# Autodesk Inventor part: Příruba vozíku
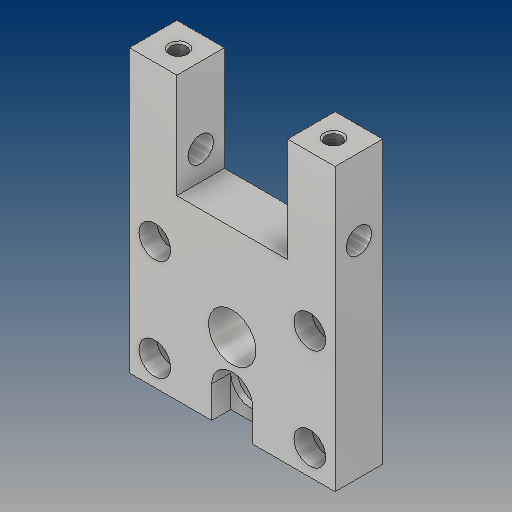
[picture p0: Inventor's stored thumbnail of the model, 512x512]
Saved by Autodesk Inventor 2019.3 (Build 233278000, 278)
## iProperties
Created: 2019-01
Part Number: Příruba vozíku
Material: Hliník 6061-AHC
Document SubType Name: Modeling
Designer: B-hon
Density: 2.7 g/cm^3
Appearance: Hliník – tmavý
Stock Number: 19-A4-P-21
Mass: 163.521 g
Surface Area: 177.073 cm^2
Volume: 60.5633 cm^3
Author: B-hon
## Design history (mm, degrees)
sketch "Náčrt1"
  geometry: L1 (-24.5, 16)-(24.5, 16); L2 (24.5, 16)-(24.5, -16); L3 (24.5, -16)-(-24.5, -16); L4 (-24.5, -16)-(-24.5, 16); L5 (-24.5, 16)-(24.5, -16); L6 (24.5, 16)-(-24.5, -16); L7 (32.5, -24)-(-32.5, -24); L8 (-32.5, -24)-(-32.5, 56); L9 (32.5, 56)-(32.5, -24); L10 (-32.5, 56)-(32.5, 56); 1 further point
  constraints: 20 end point, 3 horizontal, 3 parallel, 2 midpoint, 2 perpendicular
  dimensions: "d0" = 49 distance of L2.end L3.end; "d1" = 32 distance of L1.end L2.end; "d4" = 80 distance between parallel lines of L7 L10; "d21" = 8 distance between parallel lines of L9 L2; "d22" = 8 distance between parallel lines of L4 L8; "d23" = 8 distance between parallel lines of L7 L3
extrude "Vysunutí1" new body sketch "Náčrt1" distance "d5" = 12; taper "d6" = 0 deg
sketch "Náčrt2"
  geometry: L1 (0, 80)-(0, 0) reference; L2 (0, 0)-(-12, 0) reference; 2 further points
  dimensions: "d7" = 4.5 distance from line of L1 point (-4.5, 65); "d8" = 65 distance from line of L2 point (-4.5, 65)
hole "Díra1" sketch "Náčrt2" at (-4.5, 65) diameter "d9" = 8; stored, may be unused: countersink angle "d13" = 90 deg, drill point angle "d15" = 118 deg; dims "d10" = 6, "d11" = 4, "d12" = 2, "d14" = 8
sketch "Náčrt3"
  geometry: L1 (32.5, 56)-(-32.5, 56) reference; L2 (-17.5, 56)-(17.5, 56); L3 (17.5, 56)-(17.5, 32); L4 (17.5, 32)-(-17.5, 32); L5 (-17.5, 32)-(-17.5, 56); L6 (-32.5, -24)-(32.5, -24) reference; 1 further point
  constraints: 8 end point, 2 parallel, 1 horizontal, 1 perpendicular, 1 point on line
  dimensions: "d16" = 56 distance between parallel lines of L4 L6; "d17" = 35 distance of L3.end L4.end; "d18" = 15 distance from line of L1.end L5
extrude "Vysunutí2" cut sketch "Náčrt3" distance "d19" = 12; taper "d20" = 0 deg
sketch "Náčrt5"
  geometry: L1 (-24.5, 16)-(24.5, 16); L2 (24.5, 16)-(24.5, -16); L3 (24.5, -16)-(-24.5, -16); L4 (-24.5, -16)-(-24.5, 16); L5 (-24.5, 16)-(24.5, -16); L6 (24.5, 16)-(-24.5, -16); 5 further points
  constraints: 12 end point, 4 coincident, 2 midpoint, 2 parallel, 1 horizontal, 1 perpendicular
  dimensions: "d24" = 49 distance of L2.end L3.end; "d25" = 32 distance of L1.end L2.end
hole "Díra2" sketch "Náčrt5" at (-24.5, 16), (24.5, 16), (24.5, -16), (-24.5, -16) diameter "d26" = 5.3; stored, may be unused: countersink angle "d30" = 90 deg, drill point angle "d32" = 118 deg; dims "d27" = 6, "d28" = 10, "d29" = 5.7, "d31" = 8
node "Upravit přímo1"
sketch "Náčrt6"
  geometry: L1 (-32.5, -24)-(32.5, -24) reference; C1 r 6.5 at (0, -14); 1 further point
  constraints: 1 centre point
  dimensions: "d36" = 13 diameter of C1; "d37" = 10 distance from line of L1 C1.centre
extrude "Vysunutí3" cut sketch "Náčrt6" distance "d38" = 8; taper "d39" = 0 deg
sketch "Náčrt7"
  geometry: L1 (6.5, -48.468)-(-6.5, -48.468); L2 (-6.5, -48.468)-(-6.5, -14); L3 (-6.5, -14)-(6.5, -14); L4 (6.5, -14)-(6.5, -48.468); L5 (6.5, -48.468)-(-6.5, -14); L6 (-6.5, -48.468)-(6.5, -14); 3 further points
  constraints: 12 end point, 2 midpoint, 2 parallel, 1 horizontal, 1 horizontal alignment, 1 perpendicular, 1 other
  dimensions: "d40" = 13 distance of L2.end L3.end
extrude "Vysunutí4" cut sketch "Náčrt7" distance "d41" = 6; taper "d42" = 0 deg
node "Upravit přímo2"
sketch "Náčrt8"
  geometry: L1 (-32.5, -24)-(-6.5, -24) reference; L2 (-32.5, 65)-(-32.5, -24) reference; 2 further points
  dimensions: "d46" = 26 distance from line of L1 point (0, 2); "d47" = 32.5 distance from line of L2 point (0, 2)
hole "Díra3" sketch "Náčrt8" at (0, 2) diameter "d48" = 15; stored, may be unused: countersink angle "d52" = 90 deg, drill point angle "d54" = 118 deg; dims "d49" = 6, "d50" = 4, "d51" = 2, "d53" = 13
sketch "Náčrt10"
  geometry: L1 (15, 0)-(0, 0) reference; L2 (15, 0)-(15, 15) reference; L3 (50, 15)-(50, 0) reference; L4 (50, 15)-(65, 15) reference; 3 further points
  dimensions: "d64" = 7.5 distance from line of L1 point (8, 7.5); "d65" = 7 distance from line of L2 point (8, 7.5); "d66" = 7 distance from line of L3 point (57, 7.5); "d67" = 7.5 distance from line of L4 point (57, 7.5)
hole "Díra5" sketch "Náčrt10" at (8, 7.5), (57, 7.5) diameter "d68" = 4.917; stored, may be unused: countersink angle "d72" = 90 deg, drill point angle "d74" = 118 deg; dims "d69" = 12, "d70" = 6, "d71" = 2, "d73" = 17.1
node "Těleso1"
feature "Posunout1" dims "d35" = 9
feature "Posunout2" dims "d45" = 3
other parameters: "d33" = 0, "d34" = 0, "d43" = 0, "d44" = 0
